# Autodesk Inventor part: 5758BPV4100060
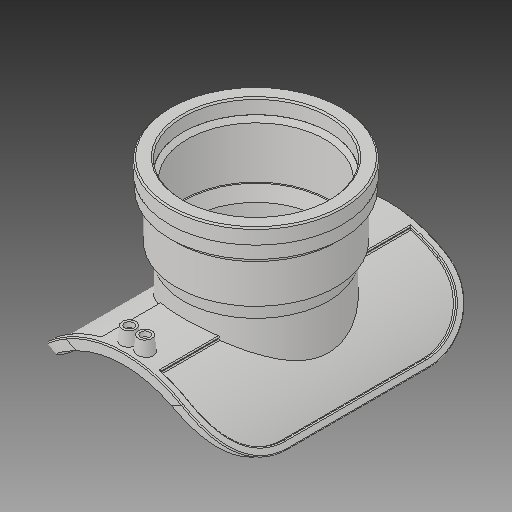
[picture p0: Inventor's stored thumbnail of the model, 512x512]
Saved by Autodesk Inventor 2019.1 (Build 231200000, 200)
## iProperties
Created: 2017-08
Part Number: 5758BPV4100060
Material: Generic
Description: PLASSON WASTEWATER SADDLE TEE 90 8''DIPS x 6''PSM for PVC
Document SubType Name: Modeling
Designer: Кирилл
Density: 1 g/cm^3
Appearance: Default
Author: Кирилл
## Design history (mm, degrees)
derived "5758BP.ipt"
feature "Solid1::5758BP.ipt"
feature "Solid2::5758BP.ipt"
feature "Solid3::5758BP.ipt"
tag "TaggingFeature1"
body "Solid1"
other parameters: "d0" = 228.9, "d1" = 224.79, "d2" = 251.79, "d3" = 289.56, "d4" = 0, "d5" = 67.437, "d6" = 7.955, "d7" = 30 deg, "d8" = 15 deg, "d10" = 0, "d11" = 148.785, "d38" = 1.1445, "d40" = 140.45, "d41" = 15, "d42" = 130.302, "d43" = 17.501, "d44" = 8.7505, "d46" = 5 deg, "d47" = 4, "d49" = 4, "d51" = 14, "d52" = 0, "d53" = 3, "d54" = 0, "d56" = 159.1, "d57" = 0.5, "d58" = 80.01, "d59" = 16.002, "d60" = 5.6007, "d61" = 40 deg, "d62" = 151.145, "d63" = 155.918, "d64" = 143.19, "d65" = 155 deg, "d66" = 124.968, "d67" = 189.992, "d68" = 188.09208, "d69" = 45 deg, "d70" = 174.546, "d72" = 7.723, "d75" = 0, "d77" = 0, "d78" = 1.591, "d81" = 37.4904, "d_" = 228.9, "B_" = 224.79, "H_" = 124.968, "L_" = 289.56, "d_1" = 159.1, "D_" = 189.992, "L_1" = 80.01, "d71" = 7.723
